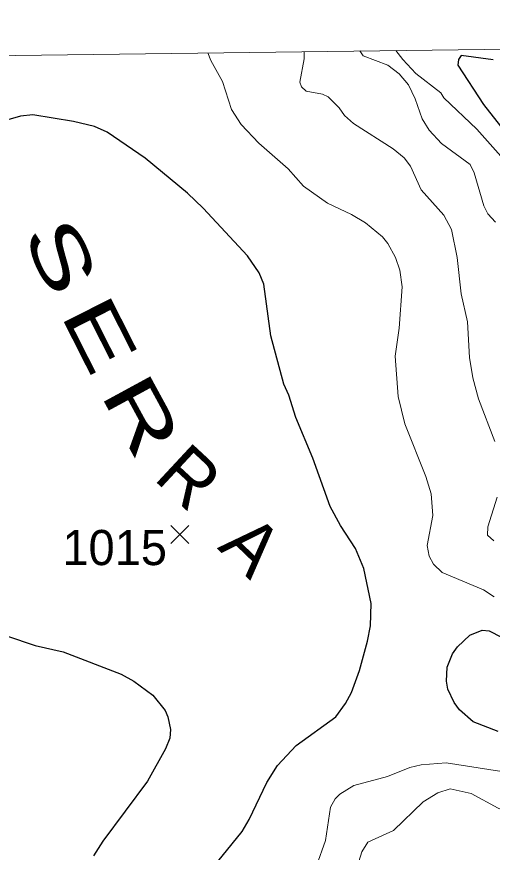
# Model space of a CAD drawing. Extents: x 265 to 291.4, y 7731.5 to 7759.6.
# Drawn here: x 278.762 to 279.844, y 7757.596 to 7759.497 of the extents above; entities that cross this region are included whole.
import ezdxf
from ezdxf.enums import TextEntityAlignment as Align

# ---------------------------------------------------------------- set-up
doc = ezdxf.new("R2010")
doc.units = 0
doc.header["$LTSCALE"] = 0.032
for name, color, linetype, lineweight in [('1', 7, 'Continuous', 25), ('2', 7, 'Continuous', 13), ('21', 7, 'Continuous', 25), ('61', 7, 'Continuous', 13), ('63', 7, 'Continuous', 25)]:
    doc.layers.add(name, color=color, linetype=linetype, lineweight=lineweight)

msp = doc.modelspace()

# ---------------------------------------------------------------- linework, layer by layer
at = {"layer": '1'}
for points in [[(279.846, 7759.3995), (279.7728, 7759.4091), (279.7673, 7759.4003), (279.7657, 7759.3868), (279.8237, 7759.2977), (279.8794, 7759.2269)], [(279.1969, 7757.5468), (279.2748, 7757.6431), (279.2908, 7757.6702), (279.3313, 7757.7545), (279.3552, 7757.7935), (279.3981, 7757.8388), (279.488, 7757.904), (279.5103, 7757.9343), (279.5238, 7757.9597), (279.5421, 7758.0091), (279.5604, 7758.0759), (279.5668, 7758.1109), (279.5684, 7758.1618), (279.5517, 7758.2413), (279.5326, 7758.2875), (279.4984, 7758.3392), (279.4753, 7758.3829), (279.4355, 7758.4927), (279.3973, 7758.585), (279.3814, 7758.6359), (279.3695, 7758.6613), (279.3401, 7758.7711), (279.3242, 7758.8889), (279.3138, 7758.9143), (279.2868, 7758.9533), (279.1865, 7759.0615), (279.1507, 7759.0957), (279.0545, 7759.1752), (278.9678, 7759.2349), (278.9392, 7759.2476), (278.8914, 7759.2587), (278.7992, 7759.2738), (278.7705, 7759.2707), (278.7419, 7759.2627)], [(278.7387, 7758.0886), (278.8039, 7758.0663), (278.8676, 7758.052), (278.9996, 7758.0011), (279.0283, 7757.9852), (279.072, 7757.9533), (279.0998, 7757.9184), (279.1062, 7757.904), (279.1118, 7757.8754), (279.1102, 7757.8555), (279.1006, 7757.8309), (279.0593, 7757.7577), (278.9582, 7757.6208), (278.9368, 7757.5874)], [(279.8572, 7757.8706), (279.8007, 7757.8929), (279.7696, 7757.9199), (279.7569, 7757.9367), (279.7432, 7757.9668), (279.7399, 7757.9854), (279.741, 7758.017), (279.7537, 7758.0472), (279.7649, 7758.0631), (279.7927, 7758.0902), (279.8206, 7758.1013), (279.8365, 7758.0997), (279.8651, 7758.0854)]]:
    msp.add_lwpolyline(points, dxfattribs=at)
at = {"layer": '2'}
for points in [[(279.4163, 7759.4178), (279.4157, 7759.4012), (279.4061, 7759.3486), (279.4101, 7759.3375), (279.4204, 7759.328), (279.4578, 7759.3208), (279.4706, 7759.3152), (279.496, 7759.2898), (279.5079, 7759.2723), (279.5286, 7759.254), (279.6185, 7759.1967), (279.6432, 7759.176), (279.6583, 7759.1569), (279.6821, 7759.1036), (279.7339, 7759.0456), (279.7513, 7759.013), (279.7641, 7758.9493), (279.7728, 7758.8666), (279.7879, 7758.8029), (279.7919, 7758.7218), (279.7999, 7758.6757), (279.8126, 7758.6279), (279.85, 7758.5309)], [(279.6845, 7759.2651), (279.6686, 7759.3105), (279.6535, 7759.3423), (279.632, 7759.3677), (279.6066, 7759.3868), (279.5501, 7759.4083), (279.5426, 7759.4194)], [(279.6243, 7759.4204), (279.6405, 7759.3997), (279.6702, 7759.3685), (279.7267, 7759.324), (279.7338, 7759.3128), (279.8086, 7759.2412), (279.8635, 7759.18)], [(279.8484, 7758.1769), (279.8238, 7758.1928), (279.7299, 7758.2326), (279.71, 7758.2517), (279.7004, 7758.27), (279.6957, 7758.2938), (279.7084, 7758.3622), (279.7052, 7758.4116), (279.6925, 7758.4513), (279.6448, 7758.5707), (279.6296, 7758.6327), (279.6233, 7758.725), (279.632, 7758.7886), (279.6392, 7758.8825), (279.6336, 7758.9207), (279.6241, 7758.9493), (279.6066, 7758.9811), (279.5946, 7758.9962), (279.5557, 7759.0281), (279.5239, 7759.0471), (279.469, 7759.0734), (279.4149, 7759.1116), (279.3799, 7759.1514), (279.313, 7759.2094), (279.2725, 7759.2524), (279.251, 7759.2866), (279.2303, 7759.3502), (279.2041, 7759.398), (279.1966, 7759.4149)], [(279.8516, 7759.0296), (279.8341, 7759.0487), (279.8245, 7759.067), (279.8031, 7759.1418), (279.7935, 7759.1609), (279.7283, 7759.2086), (279.7004, 7759.2389), (279.6845, 7759.2651)], [(279.8548, 7758.4036), (279.8341, 7758.3368), (279.8333, 7758.3177), (279.8476, 7758.3042)], [(279.5294, 7757.7481), (279.6058, 7757.768), (279.6567, 7757.7887), (279.6822, 7757.7951), (279.7394, 7757.799), (279.8603, 7757.7807), (279.9876, 7757.7823)], [(279.4443, 7757.5652), (279.4642, 7757.6224), (279.4761, 7757.6988), (279.4865, 7757.7171), (279.4968, 7757.7282), (279.5294, 7757.7481)], [(280.4824, 7757.5787), (280.4251, 7757.6041), (280.3535, 7757.6447), (280.2501, 7757.6725), (280.2056, 7757.69), (280.1388, 7757.7219), (280.0982, 7757.7258), (280.0242, 7757.7036), (279.9685, 7757.6781), (279.9351, 7757.6717), (279.9017, 7757.6773), (279.8572, 7757.6964), (279.7959, 7757.7298), (279.7482, 7757.7402), (279.7203, 7757.7314), (279.6869, 7757.7107), (279.6193, 7757.6455), (279.5612, 7757.6185), (279.5469, 7757.597), (279.5405, 7757.5747)]]:
    msp.add_lwpolyline(points, dxfattribs=at)
at = {"layer": '21'}
for p, q in [((279.1127, 7758.3398), (279.1539, 7758.2986)), ((279.1539, 7758.3398), (279.1127, 7758.2986))]:
    msp.add_line(p, q, dxfattribs=at)
at = {"layer": '63', "lineweight": 13}
msp.add_lwpolyline([(285.7494, 7759.4974), (285.2163, 7759.4908), (284.6831, 7759.4841), (284.15, 7759.4775), (283.6169, 7759.4708), (283.0837, 7759.4641), (282.5506, 7759.4574), (282.0174, 7759.4507), (281.4843, 7759.444), (280.9511, 7759.4372), (280.418, 7759.4305), (279.8848, 7759.4237), (279.3517, 7759.4169), (278.8185, 7759.4101), (278.2854, 7759.4032), (277.7522, 7759.3964), (277.2191, 7759.3895), (276.6859, 7759.3826), (276.1528, 7759.3757), (275.6196, 7759.3688), (275.0864, 7759.3619), (274.5533, 7759.355), (274.0201, 7759.348)], dxfattribs=at)

# ---------------------------------------------------------------- texts
at = {"layer": '61', "width": 1.55}
for s, rotation, p in [('S', 295.01, (278.8085, 7758.9273)), ('E', 296.846, (278.8977, 7758.7465)), ('R', 298.552, (278.9938, 7758.5605))]:
    msp.add_text(s, height=0.12, rotation=rotation, dxfattribs=at).set_placement(p, align=Align.CENTER)
at = {"layer": '61'}
for s, rotation, p in [('R', 317.095, (279.1135, 7758.4061)), ('A', 316.109, (279.2553, 7758.2507))]:
    msp.add_text(s, height=0.12, rotation=rotation, dxfattribs=at).set_placement(p, align=Align.CENTER)
msp.add_text('1015', height=0.08, dxfattribs=at).set_placement((278.985, 7758.2493), align=Align.CENTER)

doc.saveas('drawing.dxf')
